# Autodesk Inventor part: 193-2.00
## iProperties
Created: 2007-06
Part Number: 193-2.00
Document SubType Name: Modeling
Designer: btaylor
Density: 1 g/cm^3
Author: btaylor
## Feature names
1. Sweep1
2. Extrusion1
3. Extrusion2
4. Fillet1
5. Fillet2
6. Extrusion3
7. Extrusion4
8. Sweep2
9. Fillet3
10. Fillet4
11. Chamfer1
12. Chamfer2
